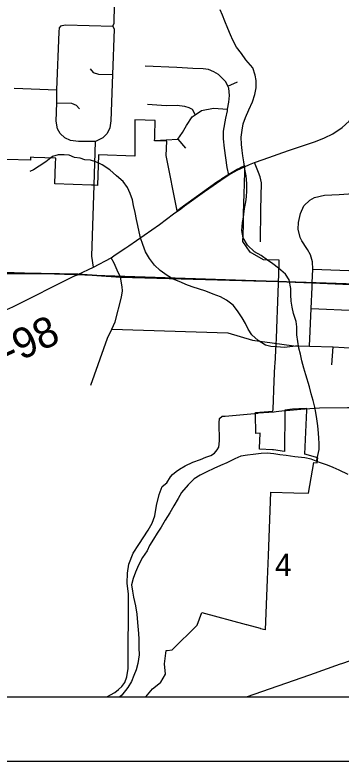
# Model space of a CAD drawing. Extents: x 0 to 34, y 0 to 22.
# Drawn here: x 5.169 to 5.78, y 14 to 15.396 of the extents above; entities that cross this region are included whole.
import ezdxf

# ---------------------------------------------------------------- set-up
doc = ezdxf.new("R2010")
doc.units = 0
for name, color, linetype in [('GM_X_City_Street', 7, 'Continuous'), ('GM_X_Corporation', 7, 'Continuous'), ('GM_X_County_Road', 7, 'Continuous'), ('GM_X_County_Road_Text', 7, 'Continuous'), ('GM_X_Minor_River', 7, 'Continuous'), ('GM_X_Section_Text', 7, 'Continuous'), ('GM_X_Township_Road', 7, 'Continuous'), ('SH_Data', 7, 'Continuous')]:
    doc.layers.add(name, color=color, linetype=linetype)

msp = doc.modelspace()

# ---------------------------------------------------------------- linework, layer by layer
at = {"layer": 'GM_X_City_Street'}
for points in [[(5.5525, 14.6413), (5.5574, 14.6453), (5.5626, 14.6458), (5.6247, 14.6512)], [(5.341, 14.1204), (5.3559, 14.1287), (5.363, 14.1338), (5.3694, 14.1396), (5.3746, 14.1472), (5.3785, 14.1579), (5.381, 14.1732), (5.3818, 14.3125), (5.3795, 14.333), (5.3796, 14.3516), (5.3824, 14.3687), (5.3907, 14.389), (5.4011, 14.4055), (5.4184, 14.432), (5.4258, 14.445), (5.4313, 14.4588), (5.434, 14.4786), (5.4389, 14.4988), (5.4448, 14.5137), (5.4538, 14.521), (5.4604, 14.5323), (5.4644, 14.5365), (5.471, 14.5422), (5.4773, 14.5462), (5.4877, 14.5525), (5.5025, 14.5593), (5.5163, 14.5647), (5.5269, 14.5685), (5.5358, 14.5718), (5.5429, 14.5765), (5.5478, 14.5826), (5.5509, 14.5878), (5.552, 14.5995), (5.5518, 14.6333), (5.5525, 14.6413)]]:
    msp.add_lwpolyline(points, dxfattribs=at)
at = {"layer": 'GM_X_Corporation'}
for points in [[(7.1023, 20.9204), (2.837, 20.9204), (2.837, 14.1204), (9.637, 14.1204), (9.637, 20.9204), (9.4036, 20.9204), (9.4022, 20.8667), (9.2273, 20.8723), (9.1354, 20.8749), (9.124, 20.8753), (8.9858, 20.878), (8.9676, 20.8785), (8.8663, 20.881), (8.6259, 20.8892), (8.5535, 20.8914), (8.5421, 20.8915), (8.4667, 20.8934), (8.0602, 20.9055), (7.9522, 20.9084), (7.1104, 20.9188)], [(5.1712, 15.9307), (6.2042, 15.8911), (6.1854, 14.88), (5.1298, 14.9148)], [(5.1073, 14.1204), (6.1556, 14.1204), (6.1854, 14.88), (5.1298, 14.9148)]]:
    msp.add_lwpolyline(points, close=True, dxfattribs=at)
for points in [[(3.4295, 14.1204), (5.4145, 14.1204), (5.427, 14.1351), (5.4415, 14.147), (5.442, 14.1479), (5.4513, 14.163), (5.4494, 14.1819), (5.452, 14.2068), (5.4541, 14.2071), (5.4637, 14.2084), (5.5104, 14.2546), (5.5193, 14.2779), (5.6024, 14.2556), (5.6027, 14.2556), (5.6286, 14.2486), (5.6289, 14.2485), (5.638, 14.2461), (5.6383, 14.246), (5.642, 14.3401), (5.6438, 14.3848), (5.6469, 14.4692), (5.6482, 14.503), (5.6912, 14.5022), (5.719, 14.5017), (5.7287, 14.5591), (5.7354, 14.5581), (5.7361, 14.5676), (5.7121, 14.5743), (5.7155, 14.6569), (5.7156, 14.6598), (5.7005, 14.6594), (5.6888, 14.6583), (5.6745, 14.657), (5.6744, 14.6542), (5.6742, 14.5794), (5.6534, 14.5823), (5.6512, 14.5824), (5.627, 14.584), (5.6271, 14.5859), (5.6286, 14.6135), (5.6201, 14.6132), (5.6197, 14.6492), (5.6197, 14.6521), (5.6523, 14.655), (5.6525, 14.6579), (5.6548, 14.7114), (5.6554, 14.7247), (5.6561, 14.74), (5.6562, 14.7428), (5.6577, 14.7686), (5.6584, 14.7805), (5.6589, 14.7899), (5.6589, 14.7909), (5.6603, 14.8267), (5.6609, 14.8435), (5.6615, 14.8603), (5.6621, 14.8772), (5.6628, 14.894), (5.6633, 14.913), (5.6638, 14.9319), (5.6639, 14.9374), (5.6348, 14.9382), (5.6096, 14.9524), (5.5961, 14.9722), (5.5964, 14.9844), (5.5969, 15.0043), (5.5974, 15.0238), (5.5979, 15.0433), (5.5984, 15.0616), (5.5989, 15.08), (5.5995, 15.1037), (5.5996, 15.1058), (5.5998, 15.1142), (5.5987, 15.1137), (5.5976, 15.1132), (5.5965, 15.1127), (5.5954, 15.1122), (5.5944, 15.1117), (5.5933, 15.1112), (5.5922, 15.1106), (5.5911, 15.1101), (5.5901, 15.1096), (5.589, 15.109), (5.5879, 15.1085), (5.5869, 15.1079), (5.5858, 15.1074), (5.5847, 15.1068), (5.5837, 15.1063), (5.5826, 15.1057), (5.5816, 15.1051), (5.5805, 15.1046), (5.5795, 15.104), (5.5784, 15.1034), (5.5774, 15.1028), (5.5763, 15.1022), (5.5753, 15.1016), (5.5743, 15.101), (5.5732, 15.1004), (5.5722, 15.0998), (5.5712, 15.0992), (5.5702, 15.0985), (5.5691, 15.0979), (5.5687, 15.0976), (5.5681, 15.0973), (5.5671, 15.0967), (5.5661, 15.096), (5.5651, 15.0954), (5.5641, 15.0947), (5.5631, 15.0941), (5.5621, 15.0934), (5.5611, 15.0928), (5.5601, 15.0921), (5.5591, 15.0914), (5.5581, 15.0907), (5.5571, 15.0901), (5.5561, 15.0894), (5.5552, 15.0887), (5.5542, 15.088), (5.5532, 15.0873), (5.5474, 15.0831), (5.478, 15.0333), (5.4766, 15.0323), (5.4731, 15.0298), (5.4526, 15.1334), (5.4535, 15.1599), (5.4307, 15.1607), (5.4309, 15.1655), (5.4311, 15.1702), (5.432, 15.1986), (5.4131, 15.1992), (5.3937, 15.1999), (5.3937, 15.1958), (5.3939, 15.1744), (5.3939, 15.1722), (5.3936, 15.1427), (5.3935, 15.1322), (5.3255, 15.1346), (5.3249, 15.1153), (5.3235, 15.0774), (5.3178, 15.0776), (5.3122, 15.0778), (5.2438, 15.0803), (5.2451, 15.1181), (5.2455, 15.1283), (5.2044, 15.1297), (5.1982, 15.13), (5.198, 15.1243), (5.1525, 15.1258)], [(8.4248, 14.7958), (7.8005, 14.8186), (7.7106, 14.8199), (7.6921, 14.8213), (7.4889, 14.8294), (6.5635, 14.8658), (6.3152, 14.8755), (6.1855, 14.8807), (5.9592, 14.8856), (5.8117, 14.8915), (5.7258, 14.8953), (5.662, 14.8972), (5.3668, 14.9059), (5.2868, 14.911), (5.2181, 14.9126), (5.1335, 14.9126)], [(5.1335, 14.9126), (5.2181, 14.9126), (5.2868, 14.911), (5.3668, 14.9059), (5.662, 14.8972), (5.7258, 14.8953), (5.8117, 14.8915), (5.9592, 14.8856), (6.1855, 14.8807), (6.3152, 14.8755), (6.5635, 14.8658), (7.4889, 14.8294), (7.6921, 14.8213), (7.7106, 14.8199), (7.8005, 14.8186), (8.4248, 14.7958)], [(3.0474, 14.1204), (9.2101, 14.1204)]]:
    msp.add_lwpolyline(points, dxfattribs=at)
at = {"layer": 'GM_X_County_Road'}
for points in [[(5.6145, 15.1191), (5.6175, 15.1203), (5.6338, 15.126), (5.6814, 15.1424), (5.732, 15.1595), (5.7488, 15.1661), (5.7643, 15.1736), (5.7818, 15.1854), (5.7952, 15.1976), (5.8068, 15.212), (5.8129, 15.2215), (5.8193, 15.2329), (5.8302, 15.2613), (5.8476, 15.3063), (5.856, 15.3274), (5.865, 15.3452), (5.879, 15.367), (5.8949, 15.3886), (5.9111, 15.406), (5.9846, 15.4793), (6.0068, 15.5016), (6.0179, 15.5128)], [(5.4797, 15.0337), (5.4869, 15.0388), (5.5243, 15.066), (5.5628, 15.0927), (5.5696, 15.0972), (5.5855, 15.1058), (5.5988, 15.1121), (5.6085, 15.1167), (5.6145, 15.1191)], [(5.3823, 14.9642), (5.4398, 15.0044), (5.4662, 15.0241), (5.4797, 15.0337)], [(5.357, 14.9471), (5.3765, 14.9602), (5.3823, 14.9642)], [(5.2862, 14.9101), (5.287, 14.9105), (5.3164, 14.9246), (5.3494, 14.942), (5.357, 14.9471)], [(5.1428, 14.8402), (5.1651, 14.8498), (5.2796, 14.9072), (5.2862, 14.9101)], [(5.7788, 14.1819), (5.7816, 14.1829), (5.8339, 14.2008), (5.8444, 14.2044)], [(5.6026, 14.1204), (5.7214, 14.1614), (5.7788, 14.1819)]]:
    msp.add_lwpolyline(points, dxfattribs=at)
at = {"layer": 'GM_X_Minor_River'}
for points in [[(5.7339, 14.5609), (5.739, 14.5832), (5.7388, 14.5942), (5.7383, 14.6045), (5.7374, 14.614), (5.7361, 14.6276), (5.7348, 14.6405), (5.7324, 14.6526), (5.7307, 14.6621), (5.7275, 14.6746), (5.7239, 14.6871), (5.7207, 14.7007), (5.714, 14.7227), (5.7104, 14.7355), (5.7064, 14.7488), (5.7039, 14.7617), (5.7011, 14.7726), (5.6991, 14.7855), (5.697, 14.798), (5.6968, 14.8129), (5.6959, 14.8227), (5.6908, 14.8379), (5.688, 14.8496), (5.6863, 14.8606), (5.6857, 14.8727), (5.686, 14.8845), (5.6827, 14.9008), (5.6761, 14.911), (5.6627, 14.9226), (5.652, 14.9308), (5.6424, 14.9375), (5.6305, 14.9461), (5.6179, 14.9531), (5.6044, 14.9654), (5.5963, 14.979), (5.5942, 14.993), (5.5955, 15.0079), (5.5969, 15.0178), (5.5993, 15.0338), (5.6014, 15.0467), (5.6025, 15.0562), (5.6031, 15.0673), (5.6036, 15.0806), (5.6019, 15.095), (5.5999, 15.1075), (5.5978, 15.1211), (5.5957, 15.1325), (5.5945, 15.1427), (5.5932, 15.1537), (5.593, 15.1674), (5.5947, 15.1807), (5.5964, 15.1925), (5.6008, 15.2044), (5.6071, 15.2185), (5.6137, 15.2338), (5.6185, 15.2472), (5.6209, 15.2601), (5.6207, 15.2738), (5.6191, 15.2837), (5.6144, 15.2973), (5.6016, 15.3123), (5.5931, 15.324), (5.5839, 15.336), (5.5769, 15.3488), (5.5726, 15.359), (5.5678, 15.3707), (5.5623, 15.3843), (5.558, 15.3957), (5.5537, 15.4059)], [(5.2999, 15.1253), (5.291, 15.1284), (5.2808, 15.1295), (5.2709, 15.1336), (5.261, 15.1344), (5.2497, 15.1343), (5.2391, 15.1316), (5.2266, 15.1217), (5.2145, 15.1133), (5.2035, 15.1064), (5.1971, 15.1034)], [(5.7004, 14.777), (5.6734, 14.7738), (5.6598, 14.7751), (5.6484, 14.7761), (5.6385, 14.7782), (5.6247, 14.7868), (5.6128, 14.798), (5.6062, 14.8086), (5.6011, 14.8187), (5.5945, 14.8293), (5.5856, 14.8428), (5.5775, 14.853), (5.5656, 14.8623), (5.5538, 14.8686), (5.5404, 14.8737), (5.5267, 14.8796), (5.5008, 14.8876), (5.4894, 14.892), (5.4798, 14.8964), (5.4653, 14.9019), (5.4542, 14.909), (5.4412, 14.9183), (5.4305, 14.928), (5.4212, 14.9405), (5.4138, 14.9529), (5.4087, 14.9665), (5.4043, 14.9794), (5.4015, 14.9907), (5.3995, 15.0021), (5.3967, 15.0134), (5.3942, 15.0263), (5.391, 15.0396), (5.389, 15.0502), (5.385, 15.0623), (5.3799, 15.0732), (5.3718, 15.0845), (5.3591, 15.0954), (5.3465, 15.1066), (5.3323, 15.1159), (5.3205, 15.1214), (5.3106, 15.1243), (5.2999, 15.1253)], [(5.7931, 14.5361), (5.7763, 14.5446), (5.7649, 14.5494), (5.7546, 14.5538), (5.7393, 14.5589), (5.7237, 14.5648), (5.7123, 14.5676), (5.6933, 14.5696), (5.6769, 14.5717), (5.6652, 14.573), (5.6541, 14.5748), (5.6416, 14.5761), (5.6302, 14.5756), (5.6151, 14.5739), (5.6048, 14.5726), (5.5924, 14.5705), (5.5807, 14.5654), (5.566, 14.5584), (5.5543, 14.5533), (5.5415, 14.5474), (5.5283, 14.5411), (5.5158, 14.5349), (5.5045, 14.5282), (5.4933, 14.5171), (5.481, 14.5024), (5.4747, 14.4913), (5.4669, 14.4776), (5.4591, 14.4645), (5.4506, 14.4507), (5.4432, 14.4381), (5.4357, 14.4266), (5.4287, 14.4155), (5.4209, 14.4032), (5.4165, 14.3936), (5.4079, 14.381), (5.4005, 14.3664), (5.395, 14.3538), (5.3906, 14.3416), (5.3874, 14.3302), (5.389, 14.318), (5.3911, 14.307), (5.3951, 14.2904), (5.3972, 14.2752), (5.3989, 14.2596), (5.4007, 14.2388), (5.4009, 14.2281), (5.4011, 14.2118), (5.4017, 14.1989), (5.3992, 14.1829), (5.396, 14.1707), (5.3919, 14.1604), (5.3875, 14.1493), (5.3805, 14.1378)], [(5.3805, 14.1378), (5.3693, 14.1236), (5.3658, 14.1204)]]:
    msp.add_lwpolyline(points, dxfattribs=at)
at = {"layer": 'GM_X_Township_Road'}
for p, q in [((5.5677, 15.2631), (5.5856, 15.2709)), ((5.1674, 15.2591), (5.2477, 15.2561)), ((5.4744, 15.1639), (5.4884, 15.1469)), ((5.3174, 15.0778), (5.3201, 15.1596)), ((5.7628, 14.7413), (5.7649, 14.7753)), ((5.6543, 14.6533), (5.6247, 14.6512))]:
    msp.add_line(p, q, dxfattribs=at)
for points in [[(5.3521, 15.3754), (5.3548, 15.3806), (5.3557, 15.4149)], [(5.3201, 15.1596), (5.288, 15.1596), (5.2729, 15.1616), (5.2622, 15.1666), (5.2539, 15.1747), (5.249, 15.1834), (5.2465, 15.1976), (5.2477, 15.2321), (5.2477, 15.2561), (5.252, 15.3645), (5.2524, 15.3722), (5.2557, 15.3759), (5.2578, 15.3764)], [(5.2578, 15.3764), (5.264, 15.3779), (5.3521, 15.3754), (5.3548, 15.3695), (5.3516, 15.2847), (5.3484, 15.1981), (5.3466, 15.1848), (5.3416, 15.1744), (5.3337, 15.1664), (5.3201, 15.1596)], [(5.3097, 15.2955), (5.3154, 15.2888), (5.3256, 15.2853), (5.3516, 15.2847)], [(5.5696, 15.0972), (5.5665, 15.1105), (5.5614, 15.1469), (5.5594, 15.1642), (5.5596, 15.1787), (5.5638, 15.203), (5.5669, 15.2166), (5.5674, 15.2197), (5.5696, 15.2333), (5.5708, 15.2458), (5.5697, 15.2591), (5.5677, 15.2631), (5.564, 15.2708), (5.5561, 15.2792), (5.5501, 15.2845), (5.5418, 15.2899), (5.5316, 15.2941), (5.5214, 15.2952), (5.5021, 15.2961), (5.4723, 15.2981), (5.4129, 15.3002)], [(5.2477, 15.2321), (5.2747, 15.231), (5.2837, 15.2273), (5.2899, 15.2206)], [(5.4176, 15.2296), (5.4524, 15.2269), (5.4731, 15.2276), (5.4868, 15.2256), (5.4947, 15.2233), (5.5011, 15.2202), (5.5067, 15.2096)], [(5.4306, 15.1613), (5.4744, 15.1639), (5.4832, 15.1763), (5.4904, 15.1896), (5.501, 15.2058), (5.5067, 15.2096), (5.5184, 15.2172), (5.5412, 15.2216), (5.5674, 15.2197)], [(5.6287, 14.9719), (5.6298, 15.0317), (5.6308, 15.0819), (5.6284, 15.0935), (5.6254, 15.1016), (5.6175, 15.1203)], [(5.7256, 14.8867), (5.726, 14.8947), (5.7271, 14.9203), (5.7265, 14.9344), (5.7224, 14.9476), (5.7171, 14.9575), (5.713, 14.9632), (5.7089, 14.9697), (5.7062, 14.9735), (5.7036, 14.9799), (5.6995, 14.9955), (5.7003, 15.0076), (5.7038, 15.0247), (5.7099, 15.0391), (5.7213, 15.0496), (5.7304, 15.0549), (5.7489, 15.059), (5.7761, 15.0601), (5.8027, 15.062), (5.8309, 15.0568), (5.8801, 15.0544), (5.9043, 15.057), (5.9149, 15.0622), (5.9367, 15.0801)], [(5.3164, 14.9246), (5.3131, 14.9448), (5.3174, 15.0778)], [(5.7271, 14.9203), (5.8116, 14.9173), (5.9589, 14.9121), (6.0104, 14.9102), (6.041, 14.9105), (6.0587, 14.9082), (6.0743, 14.9138), (6.0853, 14.921), (6.0944, 14.9331), (6.0997, 14.9452), (6.1036, 14.9596), (6.1025, 14.9698), (6.0979, 14.9755)], [(5.3661, 14.9072), (5.3626, 14.9142), (5.3586, 14.9231), (5.3546, 14.9319), (5.3494, 14.942)], [(5.3113, 14.7034), (5.3422, 14.7913), (5.3505, 14.8085), (5.357, 14.8219), (5.3689, 14.8681), (5.3706, 14.8803), (5.3696, 14.8876), (5.367, 14.9054), (5.3661, 14.9072)], [(5.7206, 14.7762), (5.7238, 14.8469), (5.7256, 14.8867)], [(5.7238, 14.8469), (5.8097, 14.8433), (5.9217, 14.8387)], [(5.3505, 14.8085), (5.5676, 14.8015), (5.6137, 14.7876), (5.6506, 14.7825)], [(5.6506, 14.7825), (5.6915, 14.7768), (5.7206, 14.7762), (5.7649, 14.7753), (5.8065, 14.7728), (5.8124, 14.7623), (5.8238, 14.7595), (5.8248, 14.7594)], [(6.171, 14.5704), (6.0841, 14.5712), (5.9242, 14.5733), (5.8248, 14.5759), (5.8177, 14.5788), (5.8156, 14.5883), (5.8263, 14.6611), (5.7917, 14.6612), (5.7392, 14.6603), (5.7126, 14.6586)], [(5.674, 14.6552), (5.6583, 14.6536), (5.6543, 14.6533)], [(5.7126, 14.6586), (5.7116, 14.6586), (5.6769, 14.6555), (5.674, 14.6552)]]:
    msp.add_lwpolyline(points, dxfattribs=at)
at = {"layer": 'SH_Data'}
msp.add_line((2.7349, 14.0001), (9.7349, 14.0001), dxfattribs=at)

# ---------------------------------------------------------------- texts
at = {"layer": 'GM_X_County_Road_Text'}
msp.add_text('C-98', height=0.05682, rotation=24.87, dxfattribs=at).set_placement((5.1077, 14.7157))
at = {"layer": 'GM_X_Section_Text'}
msp.add_text('4', height=0.0419, rotation=0, dxfattribs=at).set_placement((5.6561, 14.3462))

doc.saveas('drawing.dxf')
